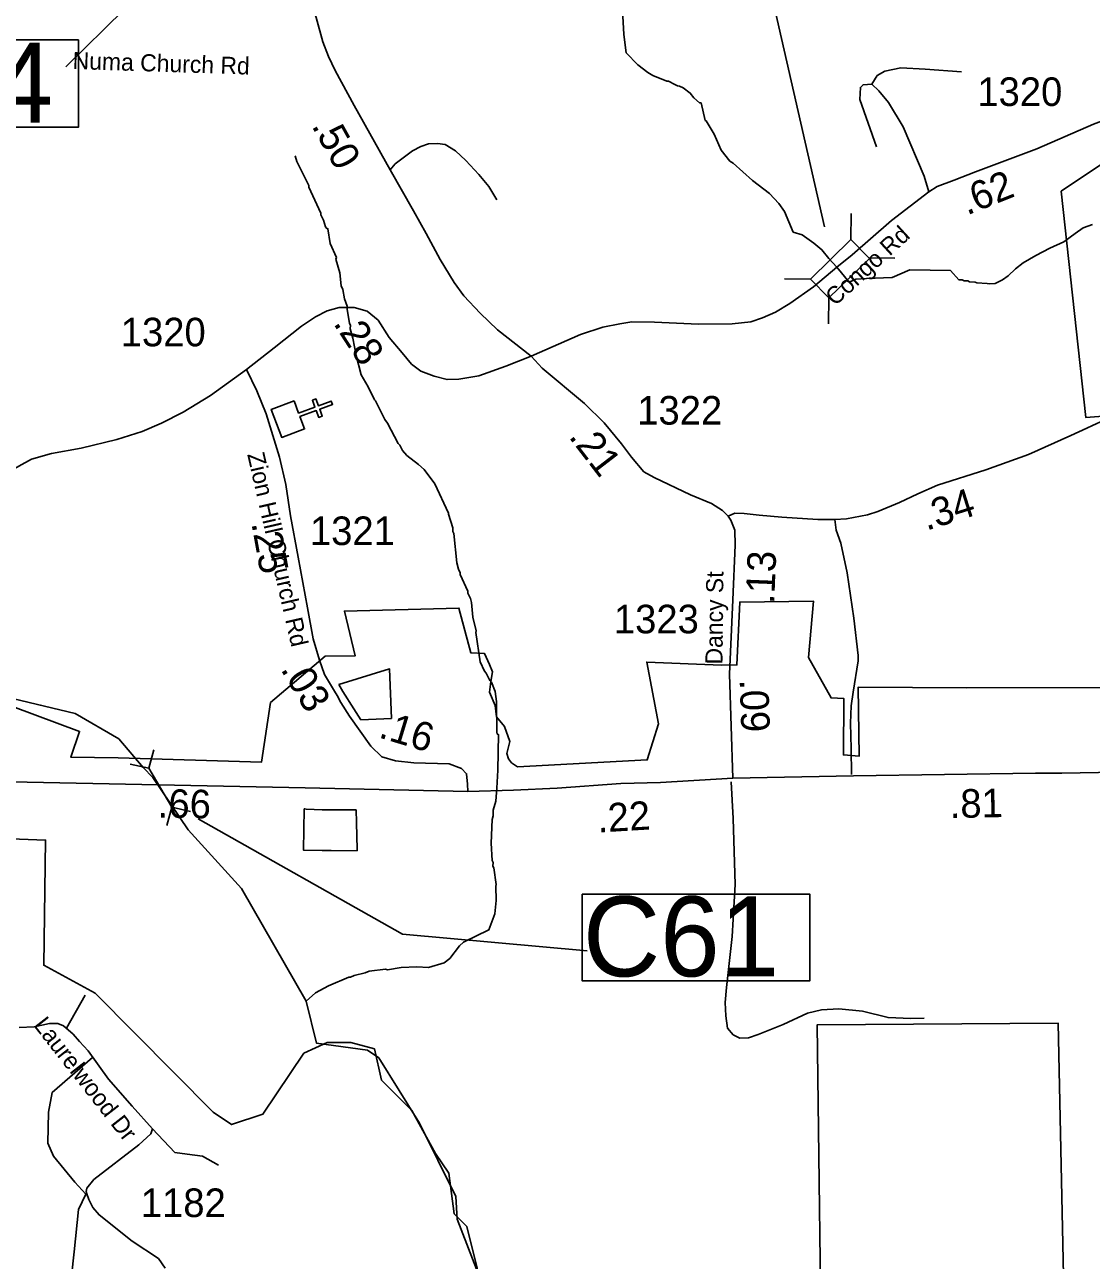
# Model space of a CAD drawing. Extents: x 1248089 to 1457196, y 820910 to 988753.
# Drawn here: x 1346272 to 1350937, y 878588 to 883995 of the extents above; entities that cross this region are included whole.
import ezdxf

# ---------------------------------------------------------------- set-up
doc = ezdxf.new("R2010")
doc.units = 0
for name, color, linetype in [('Exist Boundary Political City Limit New', 7, 'Continuous'), ('Exist Boundary Political City Limit New Hole', 7, 'Continuous'), ('Exist Cultural Church CELL', 7, 'Continuous'), ('Exist Hydrographic Creek Single Shore', 7, 'Continuous'), ('Exist Hydrographic Misc Water Feature', 7, 'Continuous'), ('Exist Road Non-System Type 51', 7, 'Continuous'), ('Exist Road Primary US Mileage Hundredths English Label', 7, 'Continuous'), ('Exist Road Primary US Structure Culvert CELL', 7, 'Continuous'), ('Exist Road Primary US Structure Culvert Number Label', 7, 'Continuous'), ('Exist Road Primary US UnDivided 4 Lane Attributed', 7, 'Continuous'), ('Exist Road Secondary Structure Standard Bridge CELL', 7, 'Continuous'), ('Exist Road Secondary Structure Standard Bridge Number Label', 7, 'Continuous'), ('Exist Road Secondary Type 51 Attributed', 7, 'Continuous'), ('Exist Road Secondary Type 51 Label', 7, 'Continuous'), ('Map Preparation Boundary City Limit Buffer Line', 7, 'Continuous'), ('Prop GRAU CAT1 Cell', 7, 'Continuous'), ('Prop Lane Lines', 7, 'Continuous')]:
    doc.layers.add(name, color=color, linetype=linetype)

msp = doc.modelspace()

# ---------------------------------------------------------------- linework, layer by layer
at = {"layer": 'Exist Boundary Political City Limit New'}
for points in [[(1350995.3, 883393.2), (1350805.8, 883265.8), (1350913.8, 882275.5), (1351102.7, 882290.8)], [(1346218.4, 881010.9), (1346512.3, 880902.3), (1346473.9, 880790.4), (1346681.5, 880787.2), (1347307.6, 880767.8), (1347347.6, 881029), (1347586.6, 881231.2), (1347717.3, 881232.7), (1347670.9, 881429), (1348171.2, 881442.2), (1348223.6, 881246), (1348283.4, 881243.5), (1348305.8, 881196.1), (1348318.3, 881163.6), (1348310.8, 881121.2), (1348305.8, 881073.8), (1348330.7, 881016.4), (1348335.7, 880966.5), (1348370.6, 880924.1), (1348394.4, 880858.5), (1348381.3, 880806.1), (1348387.9, 880783.1), (1348400.8, 880765.4), (1348427.5, 880747.8), (1348994.9, 880778.2), (1349044.2, 880936.4), (1348993.4, 881206), (1349319.3, 881191.8), (1349387.7, 881193.8), (1349399.8, 881468.4), (1349721.7, 881473.1), (1349701.2, 881226.4), (1349799.5, 881048.9), (1349855.2, 881046.5), (1349853.4, 880800), (1349921.7, 880793.8), (1349917.4, 881095.8), (1350393.3, 881093.2), (1351023.3, 881094.9)], [(1347492.8, 879495.2), (1347313.9, 879228.1), (1347177.4, 879182.6), (1347096.2, 879236.5), (1346580.2, 879758), (1346355.2, 879879.5), (1346363.9, 880427.1), (1345370.4, 880464.3)], [(1350820.9, 878315.5), (1350792.6, 879626), (1349738.1, 879618.5), (1349760.5, 877900.5)], [(1348296.6, 878372.2), (1348205.6, 878736.4), (1348151, 878791), (1348126.7, 878970.1), (1348069.1, 879055.1), (1347966, 879243.3), (1347832.5, 879376.8), (1347802.2, 879513.4), (1347699.1, 879540.7), (1347595.9, 879540.7), (1347492.8, 879495.2)]]:
    msp.add_lwpolyline(points, dxfattribs=at)
at = {"layer": 'Exist Boundary Political City Limit New Hole'}
for points in [[(1347742.3, 880953.5), (1347876.1, 880959.7), (1347868, 881176.3), (1347645.7, 881107.5)], [(1347645.7, 881107.5), (1347663.3, 881077), (1347712, 881001.8), (1347742.3, 880953.5)], [(1347573.3, 880382), (1347491.8, 880382.9), (1347494.8, 880563.3)], [(1347494.8, 880563.3), (1347497.1, 880563.2), (1347502.7, 880563), (1347572.7, 880560)], [(1347572.7, 880560), (1347615.7, 880560.1), (1347722.3, 880559.8)], [(1347722.3, 880559.8), (1347723.9, 880503.6), (1347726.1, 880385.6), (1347726.2, 880380.5)], [(1347726.2, 880380.5), (1347612.6, 880381.6), (1347573.3, 880382)]]:
    msp.add_lwpolyline(points, dxfattribs=at)
at = {"layer": 'Exist Cultural Church CELL'}
msp.add_lwpolyline([(1347450.6, 882348.5), (1347470.5, 882295.2), (1347541.9, 882321.7), (1347530.8, 882351.7), (1347545.7, 882357.3), (1347556.9, 882327.3), (1347613.3, 882348.2), (1347618.8, 882333.2), (1347562.5, 882312.2), (1347573.6, 882282.3), (1347558.6, 882276.7), (1347547.5, 882306.7), (1347476.1, 882280.2), (1347496.1, 882226.1), (1347396.3, 882189), (1347350.8, 882311.4)], close=True, dxfattribs=at)
at = {"layer": 'Exist Hydrographic Creek Single Shore'}
for points in [[(1349116, 883733.2), (1349128.2, 883726.8), (1349136.2, 883726.6), (1349152, 883718.3), (1349183.5, 883695.5), (1349199.1, 883675.2), (1349224.5, 883652.5), (1349230.5, 883652.4), (1349248.8, 883576.1), (1349252.8, 883573.6), (1349287.4, 883515.2), (1349318, 883446.5), (1349356.9, 883397.6), (1349370.7, 883389.3), (1349455, 883313.3), (1349529.7, 883255.7), (1349570.8, 883212.7), (1349596, 883178), (1349634, 883087.2), (1349672.9, 883075.5), (1349724, 883038.3), (1349759, 883010.5), (1349789.2, 882972.4), (1349824, 882934.3)], [(1349824, 882934.3), (1349878.9, 882868.1), (1349906.9, 882881.5), (1349954, 882884.9), (1350066, 882888.3), (1350144.5, 882921.9), (1350321.6, 882919.7), (1350357.4, 882878.7), (1350373.4, 882878.4), (1350381.3, 882874.2), (1350397.3, 882873.7), (1350405.2, 882869.6), (1350429.2, 882869), (1350437.2, 882864.8), (1350481.5, 882862.2)], [(1346833.4, 880700.3), (1346790.8, 880745.3), (1346684.3, 880869.9), (1346492.7, 880981), (1346187.9, 881053.5), (1345998.9, 881175.4), (1345892.9, 881292.5), (1345807, 881537.2), (1345703.7, 881775.9)], [(1350000.8, 877966.6), (1349839, 877937), (1349611.1, 877810.2), (1349438, 877531.4), (1349345, 877464.3), (1349145, 877468.3), (1348996, 877530.4), (1348865, 877634.8), (1348697.1, 877956.6), (1348298, 878420.9), (1348164, 878768.3), (1348158, 878867), (1347999, 879188.6), (1347821, 879474.4), (1347772, 879508.3), (1347548, 879539), (1347503.1, 879721.7), (1347221, 880215.3), (1346986.8, 880472.1), (1346833.4, 880700.3)]]:
    msp.add_lwpolyline(points, dxfattribs=at)
at = {"layer": 'Exist Hydrographic Misc Water Feature'}
for points in [[(1348888.2, 884031.6), (1348893.1, 883952.1), (1348903.4, 883871.9), (1348954.2, 883818.7), (1348997.5, 883785.8), (1349019.2, 883773.3), (1349080.6, 883747.9), (1349088.6, 883747.7), (1349116, 883733.2)], [(1347455.3, 883421), (1347462.8, 883396.8), (1347514.5, 883291.6), (1347514.3, 883283.6), (1347567.8, 883170.5), (1347567.6, 883162.5), (1347579.1, 883140.2), (1347588.4, 883110), (1347592.3, 883103.9), (1347598.2, 883101.8), (1347608.8, 883037.5), (1347635.4, 882976.9), (1347633.3, 882969), (1347650, 882908.6), (1347656.8, 882852.4), (1347664.4, 882836.2), (1347671.4, 882796), (1347682.8, 882763.8), (1347682.4, 882749.8), (1347693.1, 882687.6), (1347696.9, 882679.5), (1347696.5, 882663.5), (1347707.6, 882623.3), (1347722, 882546.9), (1347744.1, 882462.4), (1347774.9, 882409.7), (1347801.6, 882353.1), (1347806.5, 882348.7), (1347847.8, 882268), (1347859.5, 882251.8), (1347905.5, 882162.7), (1347913.3, 882154.5), (1347924.8, 882132.3), (1347944.3, 882109.8), (1347995.4, 882070.7), (1348018.9, 882048.1), (1348066.2, 881985.6), (1348126.6, 881857.7), (1348125.5, 881853), (1348145.3, 881793.2), (1348144.9, 881777.2), (1348148.7, 881769.1), (1348161.9, 881640.9), (1348169.3, 881612.7), (1348176.9, 881596.6), (1348176.8, 881588.6), (1348211.1, 881515.8), (1348210.9, 881507.8), (1348222.4, 881483.5), (1348226.1, 881467.4), (1348233, 881402.9), (1348247.3, 881342.9), (1348245.5, 881334.9), (1348264.2, 881206.6), (1348283.4, 881166.1), (1348291.2, 881158), (1348306.5, 881125.6), (1348314.3, 881117.4), (1348329.4, 881077.1), (1348336.4, 881032.9), (1348337.5, 880900.8), (1348339.3, 880890.8), (1348345.2, 880888.7), (1348341.7, 880732.8), (1348336.7, 880654.3), (1348332.7, 880597), (1348321.9, 880557.3), (1348321.3, 880533.3), (1348317, 880517.4), (1348312.7, 880413.4), (1348317, 880337.4), (1348320.8, 880329.3), (1348320.4, 880313.3), (1348324.3, 880305.2), (1348334.7, 880233), (1348332.5, 880225), (1348333.7, 880162.7), (1348327.9, 880105.1), (1348302.3, 880033.7), (1348191, 879980.3), (1348174.7, 879964.6), (1348131.5, 879909.6), (1348107.1, 879890.1), (1348038.6, 879869.7), (1347986.7, 879872.9), (1347918.9, 879870.1), (1347858.4, 879859.8), (1347850.4, 879862), (1347778.3, 879853.6), (1347762.1, 879846.1), (1347713.9, 879835.1), (1347697.7, 879827.5), (1347689.7, 879827.7), (1347600.8, 879789.7), (1347544.2, 879759), (1347503.1, 879721.7)], [(1350481.5, 882862.2), (1350493, 882861.5), (1350517, 882863.1), (1350549.4, 882878.3), (1350573.8, 882895.8), (1350606.5, 882927), (1350639, 882952.3), (1350694.7, 882985.5), (1350756.5, 883017.6), (1350817.1, 883044.1), (1350867.4, 883080.7)], [(1350867.4, 883080.7), (1350902.5, 883106.3), (1350942.8, 883121.3)]]:
    msp.add_lwpolyline(points, dxfattribs=at)
at = {"layer": 'Exist Road Non-System Type 51'}
msp.add_line((1346455.3, 879603.8), (1346537.3, 879748.6), dxfattribs=at)
for points in [[(1346707.1, 884061.5), (1346452.5, 883810.6)], [(1349977, 883734.6), (1350000.7, 883772.4), (1350033.8, 883791.4), (1350104.7, 883805.6), (1350211.1, 883800.8), (1350369.6, 883789)], [(1350227.5, 883264.1), (1350206.4, 883332.2), (1350114.2, 883547.6), (1350050.3, 883654.1), (1350007.8, 883706.2), (1349977, 883734.6), (1349939.2, 883732.2), (1349927.3, 883720.4), (1349925, 883668.3), (1349998.3, 883460)], [(1347870.9, 883359.5), (1347892.4, 883385.9), (1347968.9, 883442.5), (1348005.4, 883462.5), (1348038.3, 883474.3), (1348078.4, 883475.4), (1348111.3, 883470.7), (1348156, 883443.6), (1348201.9, 883400.1), (1348258.4, 883340), (1348302, 883287), (1348337.3, 883228.1)], [(1349889.2, 880714.4), (1349886.8, 880828), (1349884.5, 880939.2), (1349886.8, 881015), (1349896.3, 881074.1), (1349917.6, 881211.4), (1349917.6, 881235.1), (1349898.7, 881398.4), (1349870.3, 881597.2), (1349842.2, 881726.2), (1349820.9, 881783), (1349816.2, 881830.3)], [(1349362.2, 880681.3), (1349370.9, 880521.3), (1349379.6, 880233.2), (1349367.2, 880005.4), (1349341.9, 879782.4), (1349336.6, 879717.1), (1349339.2, 879658.4), (1349345.9, 879603.8), (1349371.2, 879574.5), (1349400.5, 879559.8), (1349437.8, 879561.2), (1349480.4, 879575.8), (1349589.6, 879619.8), (1349696.1, 879670.4), (1349757.4, 879683.8), (1349833.3, 879689.1), (1349937.2, 879678.4), (1350049, 879650.4), (1350148.3, 879646.5), (1350206.9, 879647.8)], [(1346568.4, 879475.8), (1346392.5, 879323.2), (1346376.8, 879237.2), (1346372.9, 879100.3), (1346398.3, 879043.5), (1346492.2, 878930.1), (1346539.1, 878877.3)], [(1346831.6, 879163.4), (1346928.3, 879060.1), (1346983, 879052.2), (1347049.4, 879044.4), (1347119.8, 879005.3)], [(1346539.1, 878877.3), (1346507.8, 878810.8), (1346488.2, 878624.9), (1346476.6, 878519)]]:
    msp.add_lwpolyline(points, dxfattribs=at)
at = {"layer": 'Exist Road Primary US Structure Culvert CELL'}
for p, q in [((1346837.5, 880821.8), (1346814.7, 880741.7)), ((1346733.5, 880760), (1346814.7, 880741.7)), ((1346814.7, 880741.7), (1346916.1, 880571.2)), ((1346893.4, 880491), (1346916.1, 880571.2)), ((1346997.4, 880552.8), (1346916.1, 880571.2))]:
    msp.add_line(p, q, dxfattribs=at)
at = {"layer": 'Exist Road Primary US Structure Culvert Number Label'}
msp.add_lwpolyline([(1347030.8, 880520.1), (1347924.9, 880015.3), (1348732.5, 879943.2)], dxfattribs=at)
msp.add_lwpolyline([(1348710.7, 880190.8), (1349706.1, 880190.8), (1349706.1, 879811), (1348710.7, 879811)], close=True, dxfattribs=at)
at = {"layer": 'Exist Road Primary US UnDivided 4 Lane Attributed'}
for points in [[(1353632, 880750.5), (1353050.9, 880758.3), (1352562.9, 880758.1), (1351932.8, 880741), (1350808.4, 880720.6), (1350693.8, 880720.6), (1349897.6, 880708.1), (1349369.9, 880698)], [(1348210.7, 880640.1), (1347499.5, 880656.2), (1346855.7, 880668.8), (1346211.8, 880681.7), (1345764.7, 880691.7), (1345217.5, 880704.3), (1344730.4, 880716)], [(1349369.9, 880698), (1349053.2, 880679.2), (1348880.4, 880675.4), (1348601.1, 880654.1), (1348410.8, 880645.3), (1348210.7, 880640.1)]]:
    msp.add_lwpolyline(points, dxfattribs=at)
at = {"layer": 'Exist Road Secondary Structure Standard Bridge CELL'}
for p, q in [((1349886.4, 883055), (1349887.6, 883168.1)), ((1349965.5, 882974.1), (1350078.7, 882972.9)), ((1349595.7, 882883.2), (1349708.9, 882881.9)), ((1349788.6, 882686), (1349789.9, 882799.2))]:
    msp.add_line(p, q, dxfattribs=at)
msp.add_lwpolyline([(1349708.9, 882881.9), (1349886, 883055.3), (1349967, 882972.6), (1349789.9, 882799.2)], close=True, dxfattribs=at)
at = {"layer": 'Exist Road Secondary Structure Standard Bridge Number Label'}
msp.add_lwpolyline([(1349770.7, 883110.6), (1349199.7, 885616.6), (1348026, 886695.1)], dxfattribs=at)
msp.add_lwpolyline([(1345862.9, 883928.2), (1346507, 883928.2), (1346507, 883545.9), (1345862.9, 883545.9)], close=True, dxfattribs=at)
at = {"layer": 'Exist Road Secondary Type 51 Attributed'}
for points in [[(1348487.4, 882544.8), (1348340, 882659.8), (1348264.4, 882733.4), (1348192.8, 882809.1), (1348151, 882866.8), (1348089.7, 882967.4), (1348028, 883080.9), (1347972.3, 883180.4), (1347870.9, 883359.5), (1347714, 883641.1), (1347630.5, 883794.3), (1347600.6, 883856.1), (1347576.8, 883919.7), (1347547, 884026.7), (1347503.3, 884168), (1347469.4, 884281.5), (1347443.6, 884349.2), (1347406.3, 884426), (1347379.9, 884470.6), (1347338.2, 884560.2), (1347288.5, 884685.6), (1347264.6, 884745.3), (1347227.2, 884822.8)], [(1349824, 882934.3), (1349891.5, 882987.3), (1350064.3, 883137.5), (1350227.5, 883264.1), (1350263.8, 883286.9), (1350338.1, 883314.2), (1350430.6, 883350.6), (1350698.8, 883452.2), (1350946.6, 883559.4), (1351090.6, 883614), (1351180, 883638.3), (1351278.6, 883670.2), (1351345.3, 883692.9), (1351386.2, 883715.7), (1351413.5, 883736.9), (1351431.5, 883754.8)], [(1348487.4, 882544.8), (1348702.6, 882638.9), (1348801.2, 882670.7), (1348875.4, 882685.9), (1348928.5, 882695), (1349027, 882693.5), (1349219.5, 882684.4), (1349366.5, 882685.9), (1349448.3, 882695), (1349499.9, 882711.7), (1349556, 882737.5), (1349618.7, 882775), (1349721.8, 882847.8), (1349824, 882934.3)], [(1347242, 882485.7), (1347363.6, 882580.6), (1347482.7, 882675.5), (1347543.5, 882716.9), (1347594.5, 882743.6), (1347648, 882758.2), (1347713.6, 882758.2), (1347769.6, 882741.2), (1347818.2, 882702.3), (1347866.8, 882626.8), (1347922.7, 882558.7), (1347964, 882510.1), (1348005.4, 882478.4), (1348063.7, 882456.5), (1348119.6, 882441.9), (1348170.7, 882444.4), (1348258.2, 882459), (1348377.3, 882500.3), (1348487.4, 882544.8)], [(1349348.9, 881844.5), (1349325, 881869.2), (1349276.4, 881899.6), (1349184.6, 881937.9), (1349025.3, 882013.4), (1348980.4, 882038.9), (1348926.9, 882102.2), (1348881.9, 882160.6), (1348806.5, 882253), (1348720.4, 882337.7), (1348535.7, 882492.2), (1348487.4, 882544.8)], [(1345703.7, 881775.9), (1345878, 881850.1), (1345966.3, 881888.1), (1346048.6, 881943.4), (1346149.2, 882008.5), (1346246.1, 882062.5), (1346301.3, 882093.2), (1346389.7, 882119), (1346519.8, 882142.3), (1346674.8, 882179.9), (1346786.5, 882215.5), (1346870, 882251.2), (1346965.7, 882299.1), (1347084.7, 882372.7), (1347242, 882485.7)], [(1347242, 882485.7), (1347288.1, 882393.3), (1347328.6, 882292.6), (1347386.3, 882102.2), (1347414.5, 881982.5), (1347434.1, 881846.2), (1347468.5, 881665.6), (1347508.9, 881442.7), (1347533.4, 881308.3), (1347561.6, 881213.7), (1347583.7, 881152.3), (1347627.4, 881079.3)], [(1351044.1, 882287.1), (1350942.8, 882240.6), (1350918.2, 882229.2)], [(1350918.2, 882229.2), (1350848.7, 882197), (1350662.8, 882114.3), (1350475.6, 882047.4), (1350264.4, 881980.7), (1350178.1, 881941.7), (1350099.1, 881904), (1350003.5, 881865.3), (1349958.5, 881850.7), (1349866.1, 881832.5), (1349816.2, 881830.3), (1349740.9, 881830), (1349584.1, 881839.8), (1349484.9, 881849.5), (1349419.2, 881856.8), (1349377.9, 881858), (1349348.9, 881844.5)], [(1349348.9, 881844.5), (1349361.1, 881827.6), (1349378, 881783), (1349379.6, 881717.7), (1349370.3, 881478), (1349354.6, 881153.8)], [(1349354.6, 881153.8), (1349369.9, 880698)], [(1347627.4, 881079.3), (1347638.9, 881060.2), (1347655.6, 881029.7), (1347692.8, 880969.6), (1347786.8, 880838), (1347834.2, 880791.7), (1347894.4, 880773.5), (1347974, 880765), (1348128.2, 880761.1), (1348183.2, 880740.5), (1348205.2, 880717.1), (1348209.2, 880671.7), (1348210.7, 880640.1)], [(1346248.3, 879606.9), (1346313.4, 879610.6), (1346380.7, 879624.1), (1346416.5, 879624.1), (1346441.3, 879614.4), (1346484, 879577.4), (1346512.2, 879545.5), (1346549.6, 879504.8), (1346639.4, 879380.4), (1346742.1, 879262.4), (1346831.6, 879163.4), (1346824.5, 879141.4), (1346771.7, 879093.5), (1346575.3, 878942.4), (1346544.7, 878904.6), (1346541, 878889.9), (1346544.7, 878878.8), (1346553.3, 878854.2), (1346570.5, 878819.9), (1346597.5, 878786.7), (1346742.1, 878672.3), (1346857.4, 878595.6), (1346886.8, 878553.8)]]:
    msp.add_lwpolyline(points, dxfattribs=at)
at = {"layer": 'Map Preparation Boundary City Limit Buffer Line'}
for points in [[(1350995.3, 883393.2), (1350805.8, 883265.8), (1350913.8, 882275.5), (1351102.7, 882290.8)], [(1346218.4, 881010.9), (1346512.3, 880902.3), (1346473.9, 880790.4), (1346681.5, 880787.2), (1347307.6, 880767.8), (1347347.6, 881029), (1347586.6, 881231.2), (1347717.3, 881232.7), (1347670.9, 881429), (1348171.2, 881442.2), (1348223.6, 881246), (1348283.4, 881243.5), (1348305.8, 881196.1), (1348318.3, 881163.6), (1348310.8, 881121.2), (1348305.8, 881073.8), (1348330.7, 881016.4), (1348335.7, 880966.5), (1348370.6, 880924.1), (1348394.4, 880858.5), (1348381.3, 880806.1), (1348387.9, 880783.1), (1348400.8, 880765.4), (1348427.5, 880747.8), (1348994.9, 880778.2), (1349044.2, 880936.4), (1348993.4, 881206), (1349319.3, 881191.8), (1349387.7, 881193.8), (1349399.8, 881468.4), (1349721.7, 881473.1), (1349701.2, 881226.4), (1349799.5, 881048.9), (1349855.2, 881046.5), (1349853.4, 880800), (1349921.7, 880793.8), (1349917.4, 881095.8), (1350393.3, 881093.2), (1351023.3, 881094.9)], [(1347492.8, 879495.2), (1347313.9, 879228.1), (1347177.4, 879182.6), (1347096.2, 879236.5), (1346580.2, 879758), (1346355.2, 879879.5), (1346363.9, 880427.1), (1345370.4, 880464.3)], [(1350820.9, 878315.5), (1350792.6, 879626), (1349738.1, 879618.5), (1349760.5, 877900.5)], [(1348296.6, 878372.2), (1348205.6, 878736.4), (1348151, 878791), (1348126.7, 878970.1), (1348069.1, 879055.1), (1347966, 879243.3), (1347832.5, 879376.8), (1347802.2, 879513.4), (1347699.1, 879540.7), (1347595.9, 879540.7), (1347492.8, 879495.2)]]:
    msp.add_lwpolyline(points, dxfattribs=at)

# ---------------------------------------------------------------- texts
at = {"layer": 'Exist Road Primary US Mileage Hundredths English Label'}
for s, rotation, p in [('.66', 358.8816, (1346853.3, 880526)), ('.81', 1.0407, (1350319.3, 880523.5)), ('.22', 3.405, (1348779.7, 880460))]:
    msp.add_text(s, height=125, rotation=rotation, dxfattribs=at).set_placement(p)
at = {"layer": 'Exist Road Primary US Structure Culvert Number Label'}
msp.add_text('C61', height=350, dxfattribs=at).set_placement((1348713.9, 879830.8))
at = {"layer": 'Exist Road Secondary Structure Standard Bridge Number Label'}
msp.add_text('74', height=350, dxfattribs=at).set_placement((1345875.4, 883565.7))
at = {"layer": 'Exist Road Secondary Type 51 Label'}
for s, rotation, p in [('Numa Church Rd', 358.1813, (1346481, 883801.2)), ('Congo Rd', 42.4553, (1349816.8, 882761.2)), ('Zion Hill Church Rd', 282.9209, (1347245.2, 882115)), ('Dancy St', 89.3933, (1349324.2, 881195.2)), ('Laurelwood Dr', 308.0189, (1346308, 879616.8))]:
    msp.add_text(s, height=75, rotation=rotation, dxfattribs=at).set_placement(p)
at = {"layer": 'Prop GRAU CAT1 Cell'}
for s, rotation, p in [('.50', 299.1259, (1347525.3, 883552.8)), ('.62', 21.7044, (1350393.6, 883159.9)), ('.28', 302.8075, (1347619.9, 882688.3)), ('.21', 307.604, (1348648.7, 882191.5)), ('.34', 17.5367, (1350216.4, 881780.4)), ('.25', 280.275, (1347263.4, 881813.7)), ('.13', 87.7991, (1349550.5, 881458.6)), ('.03', 300.9432, (1347389.5, 881174.9)), ('.09', 271.9309, (1349399.4, 881129.3)), ('.16', 343.1604, (1347815.9, 880877.3))]:
    msp.add_text(s, height=125, rotation=rotation, dxfattribs=at).set_placement(p)
at = {"layer": 'Prop Lane Lines'}
for s, p in [('1320', (1350439, 883639.3)), ('1320', (1346692.3, 882587.6)), ('1322', (1348951.2, 882245.1)), ('1321', (1347519.7, 881718)), ('1323', (1348849.1, 881331.8)), ('1182', (1346780, 878777.7))]:
    msp.add_text(s, height=125, dxfattribs=at).set_placement(p)

doc.saveas('drawing.dxf')
